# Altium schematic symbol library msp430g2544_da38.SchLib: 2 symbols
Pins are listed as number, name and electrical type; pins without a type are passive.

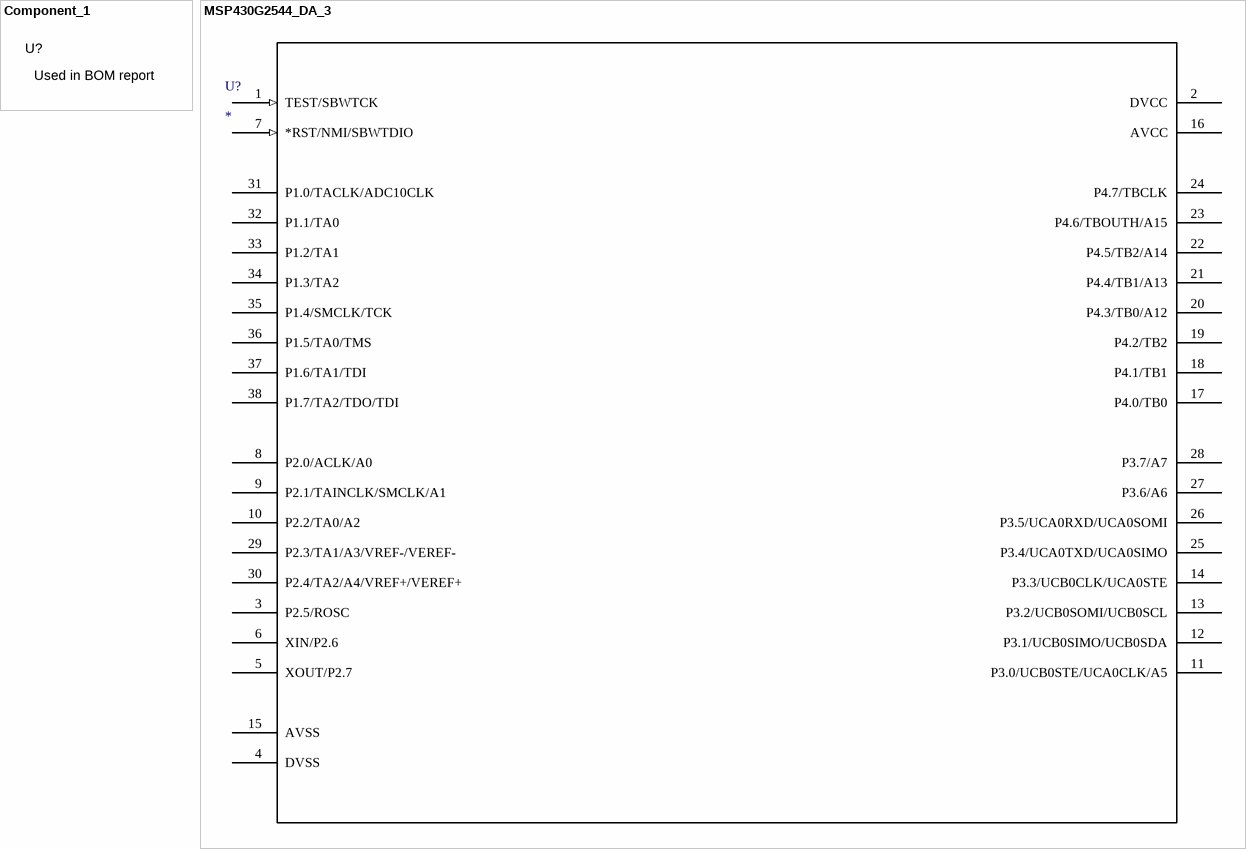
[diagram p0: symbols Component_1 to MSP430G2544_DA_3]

## Component_1
designator U?, comment Used in BOM report
SymbolVersion: use current date i.e. 2008-05-20; SymbolCreator: Use a-id; CompType: Used in some BOM reports.  Useful for finding later.; U/M: EA, IN, or GM

## MSP430G2544_DA_3
designator U?
Imported; Manufacturer_Part_Number: msp430g2544_da_38; Vendor: TEXAS INSTRUMENTS
footprint DA38
pins: 1 TEST/SBWTCK (in), 2 DVCC (power), 3 P2.5/ROSC, 4 DVSS (power), 5 XOUT/P2.7, 6 XIN/P2.6, 7 *RST/NMI/SBWTDIO (in), 8 P2.0/ACLK/A0, 9 P2.1/TAINCLK/SMCLK/A1, 10 P2.2/TA0/A2, 11 P3.0/UCB0STE/UCA0CLK/A5, 12 P3.1/UCB0SIMO/UCB0SDA, 13 P3.2/UCB0SOMI/UCB0SCL, 14 P3.3/UCB0CLK/UCA0STE, 15 AVSS (power), 16 AVCC (power), 17 P4.0/TB0, 18 P4.1/TB1, 19 P4.2/TB2, 20 P4.3/TB0/A12, 21 P4.4/TB1/A13, 22 P4.5/TB2/A14, 23 P4.6/TBOUTH/A15, 24 P4.7/TBCLK, 25 P3.4/UCA0TXD/UCA0SIMO, 26 P3.5/UCA0RXD/UCA0SOMI, 27 P3.6/A6, 28 P3.7/A7, 29 P2.3/TA1/A3/VREF-/VEREF-, 30 P2.4/TA2/A4/VREF+/VEREF+, 31 P1.0/TACLK/ADC10CLK, 32 P1.1/TA0, 33 P1.2/TA1, 34 P1.3/TA2, 35 P1.4/SMCLK/TCK, 36 P1.5/TA0/TMS, 37 P1.6/TA1/TDI, 38 P1.7/TA2/TDO/TDI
